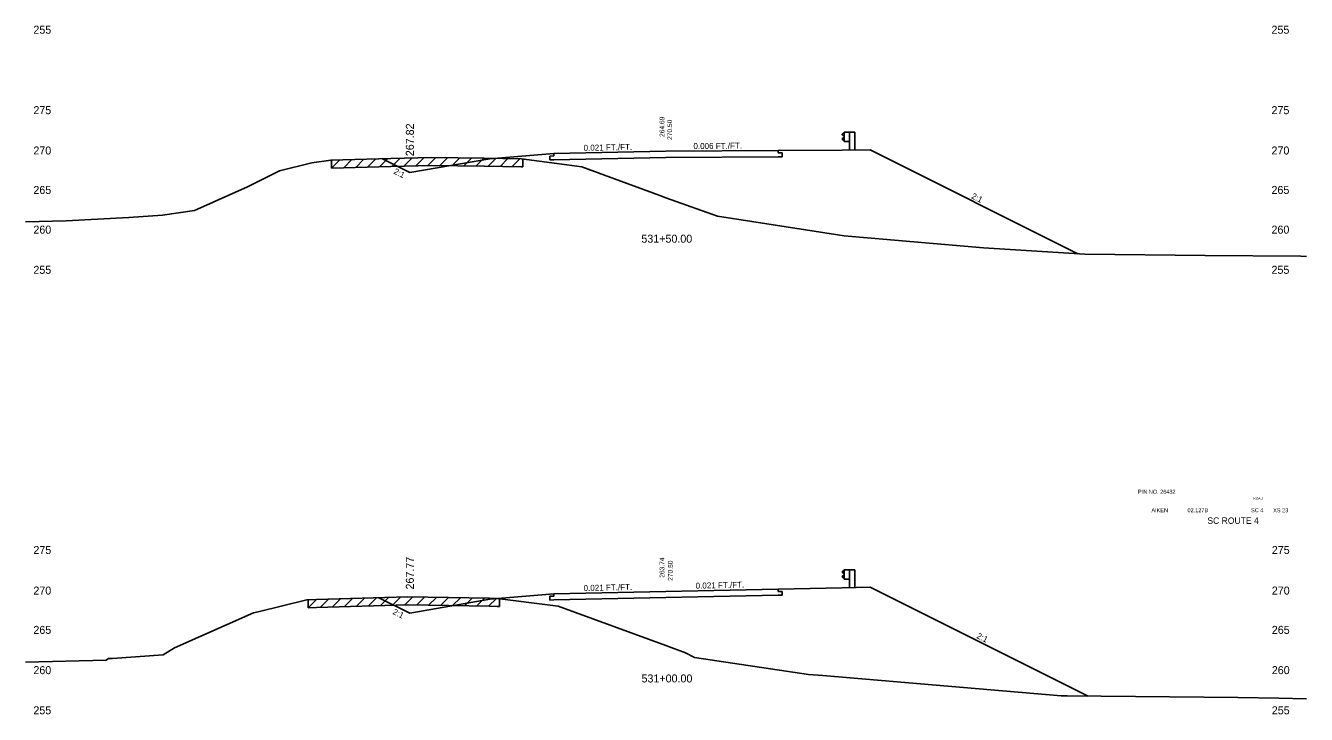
# Model space of a CAD drawing. Extents: x 883 to 1160, y 1002 to 4323.
# Drawn here: x 1000 to 1160, y 3605.1 to 3691.2 of the extents above; entities that cross this region are included whole.
import ezdxf

# ---------------------------------------------------------------- set-up
doc = ezdxf.new("R2010")
doc.units = 0
for name, color, linetype in [('Level 1', 7, 'Continuous'), ('Level 10', 7, 'Continuous'), ('Level 11', 7, 'Continuous'), ('Level 12', 7, 'Continuous'), ('Level 24', 7, 'Continuous'), ('Level 3', 7, 'Continuous'), ('Level 32', 7, 'Continuous'), ('Level 33', 7, 'Continuous'), ('Level 59', 7, 'Continuous'), ('Level 6', 7, 'Continuous'), ('Level 60', 7, 'Continuous'), ('Level 61', 7, 'Continuous'), ('Level 7', 7, 'Continuous')]:
    doc.layers.add(name, color=color, linetype=linetype)

msp = doc.modelspace()

# ---------------------------------------------------------------- linework, layer by layer
at = {"layer": 'Level 11'}
for p, q in [((1066, 3675.21), (1066, 3674.91)), ((1094, 3675.29), (1094, 3675.59)), ((1094.5, 3675.29), (1094, 3675.29)), ((1094.5, 3674.81), (1094.5, 3675.29)), ((1066, 3674.91), (1065.5, 3674.9)), ((1065.5, 3674.9), (1065.5, 3674.42)), ((1065.5, 3674.42), (1066, 3674.43)), ((1094, 3674.81), (1094.5, 3674.81)), ((1066, 3619.91), (1065.5, 3619.9)), ((1065.5, 3619.9), (1065.5, 3619.42)), ((1065.5, 3619.42), (1066, 3619.43)), ((1066, 3620.21), (1066, 3619.91)), ((1094, 3620.49), (1094, 3620.79)), ((1094.5, 3620.5), (1094, 3620.49)), ((1094, 3620.01), (1094.5, 3620.02)), ((1094.5, 3620.02), (1094.5, 3620.5))]:
    msp.add_line(p, q, dxfattribs=at)
at = {"layer": 'Level 12'}
for p, q in [((1080, 3674.72), (1066, 3674.43)), ((1094, 3674.81), (1080, 3674.72)), ((1080, 3619.72), (1066, 3619.43)), ((1094, 3620.01), (1080, 3619.72))]:
    msp.add_line(p, q, dxfattribs=at)
at = {"layer": 'Level 24'}
for p, q in [((1102.27, 3677.81), (1102, 3677.61)), ((1102, 3677.61), (1102, 3677.56)), ((1102, 3677.56), (1102.27, 3677.36)), ((1102, 3677.04), (1102.27, 3677.24)), ((1102, 3676.99), (1102, 3677.04)), ((1102.27, 3676.79), (1102, 3676.99)), ((1102.27, 3676.72), (1102.27, 3677.89)), ((1102.27, 3677.89), (1102.94, 3677.89)), ((1102.94, 3677.89), (1102.94, 3675.64)), ((1102.94, 3677.89), (1103.6, 3677.89)), ((1103.6, 3677.89), (1103.6, 3675.65)), ((1102.27, 3676.72), (1102.94, 3676.72)), ((1102.27, 3623.13), (1102, 3622.93)), ((1102, 3622.93), (1102, 3622.88)), ((1102, 3622.88), (1102.27, 3622.68)), ((1102, 3622.36), (1102.27, 3622.56)), ((1102.27, 3622.04), (1102.27, 3623.21)), ((1102.27, 3623.21), (1102.94, 3623.21)), ((1102.94, 3623.21), (1102.94, 3620.98)), ((1102.94, 3623.21), (1103.6, 3623.21)), ((1103.6, 3623.21), (1103.6, 3620.99)), ((1102, 3622.31), (1102, 3622.36)), ((1102.27, 3622.11), (1102, 3622.31)), ((1102.27, 3622.04), (1102.94, 3622.04))]:
    msp.add_line(p, q, dxfattribs=at)
at = {"layer": 'Level 59'}
for p, q in [((1066, 3675.21), (1080, 3675.5)), ((1080, 3675.5), (1094, 3675.59)), ((1066, 3620.21), (1080, 3620.5)), ((1080, 3620.5), (1094, 3620.79))]:
    msp.add_line(p, q, dxfattribs=at)
at = {"layer": 'Level 6'}
for p, q in [((1058, 3674.54), (1066, 3675.21)), ((1094, 3675.59), (1102, 3675.64)), ((1102, 3675.64), (1105.5, 3675.66)), ((1094, 3620.79), (1102, 3620.96)), ((1102, 3620.96), (1105.5, 3621.03)), ((1058, 3619.54), (1066, 3620.21))]:
    msp.add_line(p, q, dxfattribs=at)
at = {"layer": 'Level 60'}
for p, q in [((1031.7, 3673.05), (1035.75, 3674.04)), ((1035.75, 3674.04), (1038.14, 3674.4)), ((1038.14, 3674.4), (1045.64, 3674.61)), ((1045.64, 3674.61), (1050.7, 3674.73)), ((1050.7, 3674.73), (1057.28, 3674.64)), ((1057.28, 3674.64), (1061.96, 3674.55)), ((1061.96, 3674.55), (1066.37, 3673.98)), ((1066.37, 3673.98), (1069.47, 3673.53)), ((1027.71, 3671.06), (1031.7, 3673.05)), ((1069.47, 3673.53), (1079.25, 3669.96)), ((1021.08, 3668.11), (1027.71, 3671.06)), ((1079.25, 3669.96), (1080, 3669.69)), ((1080, 3669.69), (1086.44, 3667.37)), ((1005.06, 3666.82), (1012.88, 3667.21)), ((1012.88, 3667.21), (1017.12, 3667.51)), ((1017.12, 3667.51), (1021.08, 3668.11)), ((1086.44, 3667.37), (1095.02, 3666.06)), ((1000, 3666.68), (1005.06, 3666.82)), ((1095.02, 3666.06), (1102.25, 3664.94)), ((1102.25, 3664.94), (1119.68, 3663.42)), ((1119.68, 3663.42), (1132.34, 3662.63)), ((1132.34, 3662.63), (1147.35, 3662.47)), ((1147.35, 3662.47), (1159.29, 3662.37)), ((1159.29, 3662.37), (1160, 3662.36)), ((1029.04, 3617.95), (1035.12, 3619.43)), ((1035.12, 3619.43), (1036.33, 3619.47)), ((1036.33, 3619.47), (1047.72, 3619.8)), ((1047.72, 3619.8), (1057.93, 3619.65)), ((1057.93, 3619.65), (1058.92, 3619.63)), ((1058.92, 3619.63), (1065.88, 3618.73)), ((1018.58, 3613.44), (1028.48, 3617.84)), ((1028.48, 3617.84), (1029.04, 3617.95)), ((1065.88, 3618.73), (1066.53, 3618.64)), ((1066.53, 3618.64), (1080, 3613.74)), ((1017.17, 3612.58), (1018.58, 3613.44)), ((1080, 3613.74), (1082.44, 3612.84)), ((1082.44, 3612.84), (1083.54, 3612.24)), ((1000, 3611.64), (1010.06, 3611.92)), ((1010.06, 3611.92), (1010.36, 3612.13)), ((1010.36, 3612.13), (1010.87, 3612.13)), ((1010.87, 3612.13), (1017.17, 3612.58)), ((1083.54, 3612.24), (1097.79, 3610.1)), ((1097.79, 3610.1), (1099.58, 3609.99)), ((1099.58, 3609.99), (1129.35, 3607.44)), ((1129.35, 3607.44), (1130.11, 3607.44)), ((1130.11, 3607.44), (1151.45, 3607.22)), ((1151.45, 3607.22), (1156.56, 3607.16)), ((1156.56, 3607.16), (1160, 3607.08))]:
    msp.add_line(p, q, dxfattribs=at)
at = {"layer": 'Level 61'}
for p, q in [((1039.26, 3674.43), (1038.23, 3673.4)), ((1038.23, 3674.4), (1038.23, 3673.4)), ((1038.23, 3673.4), (1045.64, 3673.61)), ((1040.77, 3674.47), (1039.74, 3673.44)), ((1042.27, 3674.51), (1041.24, 3673.48)), ((1043.77, 3674.56), (1042.74, 3673.53)), ((1045.27, 3674.6), (1044.24, 3673.57)), ((1045.64, 3673.61), (1050.7, 3673.73)), ((1046.77, 3674.64), (1045.75, 3673.61)), ((1048.28, 3674.67), (1047.25, 3673.65)), ((1049.78, 3674.71), (1048.75, 3673.68)), ((1051.26, 3674.72), (1050.25, 3673.72)), ((1050.7, 3673.73), (1057.28, 3673.64)), ((1052.74, 3674.7), (1051.76, 3673.72)), ((1054.25, 3674.68), (1053.26, 3673.69)), ((1055.75, 3674.66), (1054.76, 3673.67)), ((1057.25, 3674.64), (1056.26, 3673.65)), ((1057.28, 3673.64), (1061.96, 3673.55)), ((1058.75, 3674.61), (1057.77, 3673.63)), ((1060.25, 3674.58), (1059.27, 3673.6)), ((1061.76, 3674.56), (1060.77, 3673.57)), ((1062.13, 3673.53), (1062.13, 3674.53)), ((1061.96, 3673.55), (1062.13, 3673.53)), ((1036.33, 3619.47), (1035.3, 3618.44)), ((1035.3, 3619.44), (1035.3, 3618.44)), ((1037.83, 3619.51), (1036.8, 3618.48)), ((1039.33, 3619.56), (1038.3, 3618.53)), ((1040.83, 3619.6), (1039.8, 3618.57)), ((1042.34, 3619.64), (1041.31, 3618.61)), ((1043.84, 3619.68), (1042.81, 3618.66)), ((1045.34, 3619.73), (1044.31, 3618.7)), ((1046.84, 3619.77), (1045.81, 3618.74)), ((1048.32, 3619.79), (1047.32, 3618.78)), ((1049.81, 3619.77), (1048.82, 3618.78)), ((1051.31, 3619.74), (1050.32, 3618.76)), ((1052.81, 3619.72), (1051.82, 3618.74)), ((1054.31, 3619.7), (1053.33, 3618.72)), ((1055.82, 3619.68), (1054.83, 3618.69)), ((1057.32, 3619.66), (1056.33, 3618.67)), ((1058.81, 3619.63), (1057.83, 3618.65)), ((1059.19, 3618.59), (1059.19, 3619.59)), ((1035.3, 3618.44), (1036.33, 3618.47)), ((1036.33, 3618.47), (1047.72, 3618.8)), ((1047.72, 3618.8), (1057.93, 3618.65)), ((1057.93, 3618.65), (1058.92, 3618.63)), ((1058.92, 3618.63), (1059.19, 3618.59))]:
    msp.add_line(p, q, dxfattribs=at)
at = {"layer": 'Level 7'}
for p, q in [((1105.5, 3675.66), (1131.45, 3662.68)), ((1044.48, 3674.58), (1048, 3672.82)), ((1048, 3672.82), (1058, 3674.54)), ((1105.5, 3621.03), (1132.74, 3607.41)), ((1044.14, 3619.69), (1048, 3617.77)), ((1048, 3617.77), (1058, 3619.54))]:
    msp.add_line(p, q, dxfattribs=at)

# ---------------------------------------------------------------- texts
at = {"layer": 'Level 1'}
for s, height, p in [('531+50.00', 1, (1076.92, 3664.07)), ('PIN NO. 26432', 0.5, (1138.97, 3632.7)), ('AIKEN', 0.5, (1140.64, 3630.39)), ('02.127B', 0.5, (1145.15, 3630.39)), ('SC 4', 0.5, (1153.09, 3630.39)), ('XS 23', 0.5, (1155.85, 3630.38)), ('SC ROUTE 4', 0.8, (1147.63, 3628.94)), ('531+00.00', 1, (1076.94, 3609.12))]:
    msp.add_text(s, height=height, dxfattribs=at).set_placement(p)
at = {"layer": 'Level 10'}
for s, p in [('264.69', (1079.8, 3677.28)), ('263.74', (1079.8, 3622.2))]:
    msp.add_text(s, height=0.6, rotation=90, dxfattribs=at).set_placement(p)
at = {"layer": 'Level 3'}
for s, height, p in [(' 255', 1, (1000.6, 3690.18)), (' 255', 1, (1155.27, 3690.18)), (' 275', 1, (1000.6, 3680.13)), (' 275', 1, (1155.27, 3680.13)), (' 270', 1, (1000.6, 3675.09)), (' 270', 1, (1155.27, 3675.09)), (' 265', 1, (1000.6, 3670.16)), (' 265', 1, (1155.27, 3670.16)), (' 260', 1, (1000.6, 3665.2)), (' 260', 1, (1155.27, 3665.2)), (' 255', 1, (1000.6, 3660.18)), (' 255', 1, (1155.27, 3660.18)), ('ROAD', 0.3, (1153.38, 3631.97)), (' 275', 1, (1000.6, 3625.17)), (' 275', 1, (1155.31, 3625.17)), (' 270', 1, (1000.6, 3620.1)), (' 270', 1, (1155.31, 3620.1)), (' 265', 1, (1000.6, 3615.19)), (' 265', 1, (1155.31, 3615.19)), (' 260', 1, (1000.6, 3610.16)), (' 260', 1, (1155.31, 3610.16)), (' 255', 1, (1000.6, 3605.14)), (' 255', 1, (1155.31, 3605.14))]:
    msp.add_text(s, height=height, dxfattribs=at).set_placement(p)
at = {"layer": 'Level 32'}
for s, rotation, p in [('0.021 FT./FT.', 1.1916, (1069.71, 3675.54)), ('0.006 FT./FT.', 0.356, (1083.43, 3675.77)), ('2:1', 333.435, (1045.9, 3672.74)), ('2:1', 333.435, (1118.08, 3669.65)), ('0.021 FT./FT.', 1.1916, (1069.71, 3620.54)), ('0.021 FT./FT.', 1.1916, (1083.71, 3620.83)), ('2:1', 333.435, (1045.78, 3617.7)), ('2:1', 333.435, (1118.73, 3614.7))]:
    msp.add_text(s, height=0.75, rotation=rotation, dxfattribs=at).set_placement(p)
at = {"layer": 'Level 33'}
for s, p in [('267.82', (1048.5, 3674.88)), ('267.77', (1048.5, 3620.74))]:
    msp.add_text(s, height=1, rotation=90, dxfattribs=at).set_placement(p)
at = {"layer": 'Level 59'}
for p in [(1080.76, 3676.68), (1080.85, 3621.59)]:
    msp.add_text(' 270.50', height=0.6, rotation=90, dxfattribs=at).set_placement(p)

doc.saveas('drawing.dxf')
